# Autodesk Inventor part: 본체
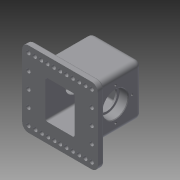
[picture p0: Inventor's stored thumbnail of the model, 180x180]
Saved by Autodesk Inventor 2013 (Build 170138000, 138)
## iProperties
Created: 2018-11
Part Number: 본체
Material: 일반
Document SubType Name: Modeling
Designer: Administrator
Density: 1 g/cm^3
Author: Administrator
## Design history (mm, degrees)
sketch "스케치1"
  geometry: L1 (60, -60)-(-60, -60); L2 (-60, -60)-(-60, 60); L3 (-60, 60)-(60, 60); L4 (60, 60)-(60, -60); 2 further points
  constraints: 8 end point, 2 parallel, 1 coincident, 1 horizontal, 1 perpendicular
  dimensions: "d0" = 120 distance of L3.end L1.start; "d2" = 120 distance between parallel lines of L2 L4; "d3" = 60 distance from line of point (0, 0) L4; "d4" = 60 distance from line of point (0, 0) L1
extrude "돌출1" new body sketch "스케치1" distance "d5" = 10; taper "d6" = 0 deg
sketch "스케치2"
  geometry: L1 (60, 60)-(-60, 60) reference; L2 (60, -60)-(60, 60) reference; L3 (-40, 40)-(40, 40); L4 (40, 40)-(40, -40); L5 (40, -40)-(-40, -40); L6 (-40, -40)-(-40, 40); 2 further points
  constraints: 8 end point, 2 parallel, 1 coincident, 1 horizontal, 1 perpendicular
  dimensions: "d7" = 80 distance between parallel lines of L4 L6; "d9" = 80 distance between parallel lines of L5 L3; "d10" = 20 distance between parallel lines of L1 L3; "d11" = 20 distance between parallel lines of L2 L4
extrude "돌출2" join sketch "스케치2" distance "d12" = 80; taper "d13" = 0 deg
sketch "스케치3"
  geometry: L1 (60, -60)-(60, 60) reference; L2 (60, 60)-(-60, 60) reference; L3 (-23, 30)-(23, 30); L4 (23, 30)-(23, -30); L5 (23, -30)-(-23, -30); L6 (-23, -30)-(-23, 30); 2 further points
  constraints: 8 end point, 2 parallel, 1 coincident, 1 horizontal, 1 perpendicular
  dimensions: "d14" = 46 distance between parallel lines of L4 L6; "d16" = 60 distance between parallel lines of L5 L3; "d17" = 30 distance between parallel lines of L2 L3; "d18" = 37 distance between parallel lines of L1 L4
extrude "돌출3" cut sketch "스케치3" distance "d19" = 80; taper "d20" = 0 deg
sketch "스케치4"
  geometry: C1 r 7.5 at (0, 0); 1 further point
  constraints: 1 centre point, 1 coincident
  dimensions: "d21" = 15 diameter of C1
extrude "돌출4" join sketch "스케치4" distance "d22" = 5; taper "d23" = 0 deg
sketch "스케치5"
  geometry: C1 r 7.5 at (0, 0) reference; C2 r 3 at (0, 0)
  constraints: 1 centre point, 1 coincident
  dimensions: "d24" = 6 diameter of C2
extrude "돌출5" cut sketch "스케치5" distance "d25" = 50; taper "d26" = 0 deg
sketch "스케치6"
  geometry: L1 (80, 0)-(0, 0) reference; L2 (80, 0)-(80, 80) reference; L3 (0, 80)-(80, 80) reference; L4 (0, 0)-(0, 80) reference; L5 (40, -10)-(40, 38); C1 r 20 at (40, 38)
  constraints: 2 end point, 1 centre point, 1 coincident, 1 parallel
  dimensions: "d27" = 48 distance of L5.start L5.end; "d28" = 40 diameter of C1
extrude "돌출6" cut sketch "스케치6" distance "d29" = 14; taper "d30" = 0 deg
sketch "스케치7"
  geometry: C1 r 20 at (0, 0) reference; C2 r 16.5 at (0, 0); 1 further point
  constraints: 1 centre point, 1 coincident
  dimensions: "d31" = 33 diameter of C2
extrude "돌출7" cut sketch "스케치7" distance "d32" = 3; taper "d33" = 0 deg
sketch "스케치9"
  geometry: L1 (40, 64)-(40, 12); C1 r 20 at (40, 38) reference; A1 r 26 centre (40, 38) between (40, 64) and (40, 12); 2 further points
  constraints: 2 coincident, 2 end point, 2 point on circle, 1 centre point
  dimensions: "d34" = 52 diameter of A1
hole "구멍1" sketch "스케치9" at (40, 64) diameter "d35" = 3.242; stored, may be unused: countersink angle "d39" = 82 deg, drill point angle "d41" = 118 deg; dims "d36" = 8, "d37" = 3.023, "d38" = 2, "d40" = 10
feature "스레드1" dims "d45" = 10, "d46" = 0
sketch "스케치10"
  geometry: L1 (-40, -40)-(-40, 40) reference; L2 (60, 60)-(-60, 60) reference; L3 (-60, 60)-(-60, -60) reference; L4 (60, -60)-(60, 60) reference; L5 (-60, 25)-(-40, 25); C1 r 3.3 at (-50, 50); C2 r 3.3 at (-39.046, 50); C3 r 3.3 at (-29.046, 50); C4 r 3.3 at (-19.046, 50); C5 r 3.3 at (-9.046, 50); C6 r 3.3 at (0, 50); C7 r 3.3 at (-50, 25); C8 r 3.3 at (-50, 0); C9 r 3.3 at (-50, -50); C10 r 3.3 at (-40, -50); C11 r 3.3 at (-30, -50); C12 r 3.3 at (-20, -50); C13 r 3.3 at (-10, -50); C14 r 3.3 at (0, -50); C15 r 3.3 at (-50, -25); C16 r 3.3 at (50, 50); C17 r 3.3 at (40, 50); C18 r 3.3 at (30, 50); C19 r 3.3 at (20, 50); C20 r 3.3 at (10, 50); C21 r 3.3 at (10, -50); C22 r 3.3 at (20, -50); C23 r 3.3 at (30, -50); C24 r 3.3 at (40, -50); C25 r 3.3 at (50, -50); C26 r 3.3 at (50, -25); C27 r 3.3 at (50, 25); C28 r 3.3 at (50, 0); 1 further point
  constraints: 28 centre point, 20 equal radius, 2 end point, 2 point on line, 1 midpoint, 1 perpendicular
  dimensions: "d54" = 6.6 diameter of C1; "d56" = 6.6 diameter of C3; "d57" = 6.6 diameter of C4; "d58" = 6.6 diameter of C5; "d59" = 6.6 diameter of C6; "d60" = 6.6 diameter of C7; "d61" = 6.6 diameter of C8; "d64" = 6.6 diameter of C15; "d67" = 35 distance between parallel lines of L2 L5; "d68" = 10 distance from line of C16.centre L2; "d69" = 10 distance from line of C16.centre L4; "d70" = 35 distance from line of C27.centre L2; "d71" = 10 distance from line of C27.centre L4; "d72" = 60 distance from line of C28.centre L2; "d73" = 10 distance from line of C28.centre L4; "d74" = 85 distance from line of C26.centre L2; "d75" = 10 distance from line of C26.centre L4; "d76" = 110 distance from line of C25.centre L2; "d77" = 10 distance from line of C25.centre L4; "d78" = 10 distance from line of C17.centre L2; "d79" = 20 distance from line of C17.centre L4; "d80" = 110 distance from line of C24.centre L2; "d81" = 20 distance from line of C24.centre L4; "d82" = 10 distance from line of C18.centre L2; "d83" = 30 distance from line of C18.centre L4; "d84" = 110 distance from line of C23.centre L2; "d85" = 30 distance from line of C23.centre L4; "d86" = 10 distance from line of C19.centre L2; "d87" = 40 distance from line of C19.centre L4; "d88" = 110 distance from line of C22.centre L2; "d89" = 40 distance from line of C22.centre L4; "d90" = 10 distance from line of C20.centre L2; "d91" = 50 distance from line of C20.centre L4; "d92" = 110 distance from line of C21.centre L2; "d93" = 50 distance from line of C21.centre L4; "d94" = 10 distance from line of C6.centre L2; "d95" = 60 distance from line of C6.centre L4; "d96" = 110 distance from line of C14.centre L2; "d97" = 60 distance from line of C14.centre L4; "d98" = 10 distance from line of C5.centre L2; "d99" = 69.04638 distance from line of C5.centre L4; "d100" = 110 distance from line of C13.centre L2; "d101" = 70 distance from line of C13.centre L4; "d102" = 10 distance from line of C4.centre L2; "d103" = 79.04638 distance from line of C4.centre L4; "d104" = 110 distance from line of C12.centre L2; "d105" = 80 distance from line of C12.centre L4; "d106" = 10 distance from line of C3.centre L2; "d107" = 89.04638 distance from line of C3.centre L4; "d108" = 110 distance from line of C11.centre L2; "d109" = 90 distance from line of C11.centre L4; "d110" = 10 distance from line of C2.centre L2; "d111" = 99.04638 distance from line of C2.centre L4; "d112" = 110 distance from line of C10.centre L2; "d113" = 100 distance from line of C10.centre L4; "d114" = 10 distance from line of C1.centre L2; "d115" = 110 distance from line of C1.centre L4; "d116" = 60 distance from line of C8.centre L2; "d117" = 110 distance from line of C8.centre L4; "d118" = 85 distance from line of C15.centre L2; "d119" = 110 distance from line of C15.centre L4; "d120" = 110 distance from line of C9.centre L2; "d121" = 110 distance from line of C9.centre L4
extrude "돌출8" cut sketch "스케치10" distance "d122" = 10; taper "d123" = 0 deg
fillet "모깎기1" dims "d124" = 3, "d125" = 8, "d126" = 10, "d127" = 0.6
fillet "모깎기2" dims "d128" = 3, "d129" = 8
sketch "스케치11"
  geometry: L1 (82, -82)-(-18, -82) reference; 2 further points
  constraints: 1 other
  dimensions: "d130" = 48 distance from line of L1 point (32, -34)
feature "엠보싱1" sketch "스케치11" dims "d0" = 120, "d2" = 120, "d3" = 60, "d4" = 60, "d16" = 60, "d131" = 0.5, "d132" = 0
chamfer "모따기1" distance "d133" = 1; stored, may be unused: second distance "d134" = 2, angle "d135" = 45 deg
node "솔리드1"
pattern_circular "원형 패턴1" dims angle "d43" = 360 deg
mirror "대칭1"
node "투영된 루프1"
